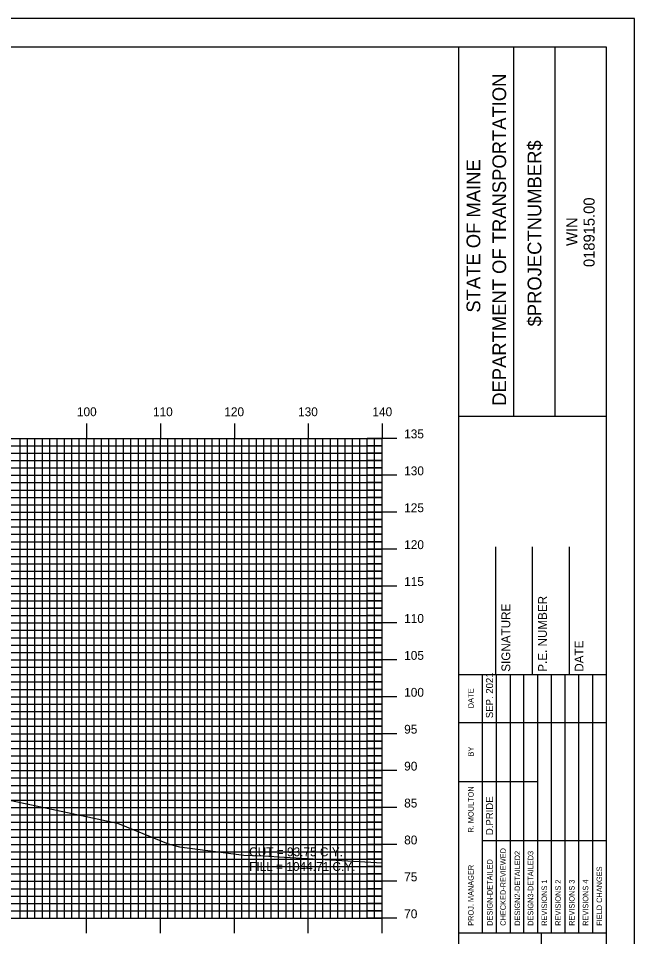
# Model space of a CAD drawing. Extents: x 858684 to 859027, y 364765 to 364985.
# Drawn here: x 858940.6 to 859024.1, y 364860.8 to 364985.2 of the extents above; entities that cross this region are included whole.
import ezdxf

# ---------------------------------------------------------------- set-up
doc = ezdxf.new("R2010")
doc.units = 0
for name, color, linetype in [('BORDER', 7, 'Continuous'), ('D_Text_Standard', 7, 'Continuous'), ('H_V ANNOTATION', 7, 'Continuous'), ('MAJOR', 7, 'Continuous'), ('MINOR', 7, 'Continuous'), ('PLOT BOUNDARY', 7, 'Continuous'), ('S_Roadway_Centerline', 7, 'Continuous')]:
    doc.layers.add(name, color=color, linetype=linetype)

msp = doc.modelspace()

# ---------------------------------------------------------------- linework, layer by layer
at = {"layer": 'BORDER'}
for p, q in [((859000.25, 364771.3), (859000.25, 364981.3)), ((859007.7, 364931.3), (859007.7, 364981.3)), ((859013.29, 364931.3), (859013.29, 364981.3)), ((859000.25, 364931.29), (859020.25, 364931.29)), ((859005.25, 364896.31), (859005.25, 364913.6)), ((859010.25, 364896.31), (859010.25, 364913.6)), ((859015.25, 364896.31), (859015.25, 364913.6)), ((859000.25, 364896.31), (859020.25, 364896.31)), ((859000.25, 364861.31), (859020.25, 364861.31)), ((859011.43, 364791.31), (859011.43, 364861.31))]:
    msp.add_line(p, q, dxfattribs=at)
msp.add_lwpolyline([(858700.25, 364771.3), (859020.25, 364771.3), (859020.25, 364981.3), (858700.25, 364981.3)], close=True, dxfattribs=at)
for points in [[(859003.48, 364889.81), (859003.48, 364896.31)], [(859005.34, 364861.31), (859005.34, 364896.31)], [(859007.21, 364896.31), (859007.21, 364861.31)], [(859009.07, 364861.31), (859009.07, 364896.31)], [(859010.93, 364861.31), (859010.93, 364896.31)], [(859012.8, 364861.31), (859012.8, 364896.31)], [(859014.66, 364861.31), (859014.66, 364896.31)], [(859016.52, 364861.31), (859016.52, 364896.31)], [(859018.39, 364861.31), (859018.39, 364896.31)], [(859003.48, 364861.31), (859003.48, 364894.9)], [(859000.25, 364889.81), (859020.25, 364889.81)], [(859000.25, 364881.81), (859003.48, 364881.81)], [(859003.48, 364881.81), (859010.93, 364881.81)], [(859003.48, 364873.81), (859020.25, 364873.81)]]:
    msp.add_lwpolyline(points, dxfattribs=at)
at = {"layer": 'MAJOR'}
for p, q in [((858949.85, 364930.31), (858949.85, 364928.3)), ((858959.85, 364930.31), (858959.85, 364928.3)), ((858969.85, 364930.31), (858969.85, 364928.3)), ((858979.85, 364930.31), (858979.85, 364928.3)), ((858989.85, 364930.31), (858989.85, 364928.3)), ((858709.85, 364928.3), (858989.85, 364928.3)), ((858709.85, 364928.3), (858989.85, 364928.3)), ((858949.85, 364863.3), (858949.85, 364928.3)), ((858959.85, 364863.3), (858959.85, 364928.3)), ((858969.85, 364863.3), (858969.85, 364928.3)), ((858979.85, 364863.3), (858979.85, 364928.3)), ((858991.85, 364928.3), (858987.84, 364928.3)), ((858989.85, 364863.3), (858989.85, 364928.3)), ((858989.85, 364863.3), (858989.85, 364928.3)), ((858709.85, 364923.3), (858989.85, 364923.3)), ((858991.85, 364923.3), (858987.84, 364923.3)), ((858709.85, 364918.3), (858989.85, 364918.3)), ((858991.85, 364918.3), (858987.84, 364918.3)), ((858709.85, 364913.3), (858989.85, 364913.3)), ((858991.85, 364913.3), (858987.84, 364913.3)), ((858709.85, 364908.3), (858989.85, 364908.3)), ((858991.85, 364908.3), (858987.84, 364908.3)), ((858709.85, 364903.3), (858989.85, 364903.3)), ((858991.85, 364903.3), (858987.84, 364903.3)), ((858709.85, 364898.3), (858989.85, 364898.3)), ((858991.85, 364898.3), (858987.84, 364898.3)), ((858709.85, 364893.3), (858989.85, 364893.3)), ((858991.85, 364893.3), (858987.84, 364893.3)), ((858709.85, 364888.3), (858989.85, 364888.3)), ((858991.85, 364888.3), (858987.84, 364888.3)), ((858709.85, 364883.3), (858989.85, 364883.3)), ((858991.85, 364883.3), (858987.84, 364883.3)), ((858709.85, 364878.3), (858989.85, 364878.3)), ((858991.85, 364878.3), (858987.84, 364878.3)), ((858709.85, 364873.3), (858989.85, 364873.3)), ((858991.85, 364873.3), (858987.84, 364873.3)), ((858709.85, 364868.3), (858989.85, 364868.3)), ((858991.85, 364868.3), (858987.84, 364868.3)), ((858709.85, 364863.3), (858989.85, 364863.3)), ((858709.85, 364863.3), (858989.85, 364863.3)), ((858949.85, 364861.3), (858949.85, 364863.3)), ((858959.85, 364861.3), (858959.85, 364863.3)), ((858969.85, 364861.3), (858969.85, 364863.3)), ((858979.85, 364861.3), (858979.85, 364863.3)), ((858991.85, 364863.3), (858987.84, 364863.3)), ((858989.85, 364861.3), (858989.85, 364863.3))]:
    msp.add_line(p, q, dxfattribs=at)
at = {"layer": 'MINOR'}
for p, q in [((858940.85, 364863.3), (858940.85, 364928.3)), ((858941.85, 364863.3), (858941.85, 364928.3)), ((858942.85, 364863.3), (858942.85, 364928.3)), ((858943.85, 364863.3), (858943.85, 364928.3)), ((858944.85, 364863.3), (858944.85, 364928.3)), ((858945.85, 364863.3), (858945.85, 364928.3)), ((858946.85, 364863.3), (858946.85, 364928.3)), ((858947.85, 364863.3), (858947.85, 364928.3)), ((858948.85, 364863.3), (858948.85, 364928.3)), ((858950.85, 364863.3), (858950.85, 364928.3)), ((858951.85, 364863.3), (858951.85, 364928.3)), ((858952.85, 364863.3), (858952.85, 364928.3)), ((858953.85, 364863.3), (858953.85, 364928.3)), ((858954.85, 364863.3), (858954.85, 364928.3)), ((858955.85, 364863.3), (858955.85, 364928.3)), ((858956.85, 364863.3), (858956.85, 364928.3)), ((858957.85, 364863.3), (858957.85, 364928.3)), ((858958.85, 364863.3), (858958.85, 364928.3)), ((858960.85, 364863.3), (858960.85, 364928.3)), ((858961.85, 364863.3), (858961.85, 364928.3)), ((858962.85, 364863.3), (858962.85, 364928.3)), ((858963.85, 364863.3), (858963.85, 364928.3)), ((858964.85, 364863.3), (858964.85, 364928.3)), ((858965.85, 364863.3), (858965.85, 364928.3)), ((858966.85, 364863.3), (858966.85, 364928.3)), ((858967.85, 364863.3), (858967.85, 364928.3)), ((858968.85, 364863.3), (858968.85, 364928.3)), ((858970.85, 364863.3), (858970.85, 364928.3)), ((858971.85, 364863.3), (858971.85, 364928.3)), ((858972.85, 364863.3), (858972.85, 364928.3)), ((858973.85, 364863.3), (858973.85, 364928.3)), ((858974.85, 364863.3), (858974.85, 364928.3)), ((858975.85, 364863.3), (858975.85, 364928.3)), ((858976.85, 364863.3), (858976.85, 364928.3)), ((858977.85, 364863.3), (858977.85, 364928.3)), ((858978.85, 364863.3), (858978.85, 364928.3)), ((858980.85, 364863.3), (858980.85, 364928.3)), ((858981.85, 364863.3), (858981.85, 364928.3)), ((858982.85, 364863.3), (858982.85, 364928.3)), ((858983.85, 364863.3), (858983.85, 364928.3)), ((858984.85, 364863.3), (858984.85, 364928.3)), ((858985.85, 364863.3), (858985.85, 364928.3)), ((858986.85, 364863.3), (858986.85, 364928.3)), ((858987.85, 364863.3), (858987.85, 364928.3)), ((858988.85, 364863.3), (858988.85, 364928.3)), ((858709.85, 364927.3), (858989.85, 364927.3)), ((858989.85, 364927.3), (858987.84, 364927.3)), ((858709.85, 364926.3), (858989.85, 364926.3)), ((858989.85, 364926.3), (858987.84, 364926.3)), ((858709.85, 364925.3), (858989.85, 364925.3)), ((858709.85, 364924.3), (858989.85, 364924.3)), ((858989.85, 364925.3), (858987.84, 364925.3)), ((858989.85, 364924.3), (858987.84, 364924.3)), ((858709.85, 364922.3), (858989.85, 364922.3)), ((858989.85, 364922.3), (858987.84, 364922.3)), ((858709.85, 364921.3), (858989.85, 364921.3)), ((858989.85, 364921.3), (858987.84, 364921.3)), ((858709.85, 364920.3), (858989.85, 364920.3)), ((858989.85, 364920.3), (858987.84, 364920.3)), ((858709.85, 364919.3), (858989.85, 364919.3)), ((858989.85, 364919.3), (858987.84, 364919.3)), ((858709.85, 364917.3), (858989.85, 364917.3)), ((858989.85, 364917.3), (858987.84, 364917.3)), ((858709.85, 364916.3), (858989.85, 364916.3)), ((858989.85, 364916.3), (858987.84, 364916.3)), ((858709.85, 364915.3), (858989.85, 364915.3)), ((858989.85, 364915.3), (858987.84, 364915.3)), ((858709.85, 364914.3), (858989.85, 364914.3)), ((858989.85, 364914.3), (858987.84, 364914.3)), ((858709.85, 364912.3), (858989.85, 364912.3)), ((858989.85, 364912.3), (858987.84, 364912.3)), ((858709.85, 364911.3), (858989.85, 364911.3)), ((858989.85, 364911.3), (858987.84, 364911.3)), ((858709.85, 364910.3), (858989.85, 364910.3)), ((858989.85, 364910.3), (858987.84, 364910.3)), ((858709.85, 364909.3), (858989.85, 364909.3)), ((858989.85, 364909.3), (858987.84, 364909.3)), ((858709.85, 364907.3), (858989.85, 364907.3)), ((858989.85, 364907.3), (858987.84, 364907.3)), ((858709.85, 364906.3), (858989.85, 364906.3)), ((858989.85, 364906.3), (858987.84, 364906.3)), ((858709.85, 364905.3), (858989.85, 364905.3)), ((858989.85, 364905.3), (858987.84, 364905.3)), ((858709.85, 364904.3), (858989.85, 364904.3)), ((858989.85, 364904.3), (858987.84, 364904.3)), ((858709.85, 364902.3), (858989.85, 364902.3)), ((858989.85, 364902.3), (858987.84, 364902.3)), ((858709.85, 364901.3), (858989.85, 364901.3)), ((858989.85, 364901.3), (858987.84, 364901.3)), ((858709.85, 364900.3), (858989.85, 364900.3)), ((858989.85, 364900.3), (858987.84, 364900.3)), ((858709.85, 364899.3), (858989.85, 364899.3)), ((858989.85, 364899.3), (858987.84, 364899.3)), ((858709.85, 364897.3), (858989.85, 364897.3)), ((858989.85, 364897.3), (858987.84, 364897.3)), ((858709.85, 364896.3), (858989.85, 364896.3)), ((858989.85, 364896.3), (858987.84, 364896.3)), ((858709.85, 364895.3), (858989.85, 364895.3)), ((858989.85, 364895.3), (858987.84, 364895.3)), ((858709.85, 364894.3), (858989.85, 364894.3)), ((858989.85, 364894.3), (858987.84, 364894.3)), ((858709.85, 364892.3), (858989.85, 364892.3)), ((858989.85, 364892.3), (858987.84, 364892.3)), ((858709.85, 364891.3), (858989.85, 364891.3)), ((858989.85, 364891.3), (858987.84, 364891.3)), ((858709.85, 364890.3), (858989.85, 364890.3)), ((858989.85, 364890.3), (858987.84, 364890.3)), ((858709.85, 364889.3), (858989.85, 364889.3)), ((858989.85, 364889.3), (858987.84, 364889.3)), ((858709.85, 364887.3), (858989.85, 364887.3)), ((858989.85, 364887.3), (858987.84, 364887.3)), ((858709.85, 364886.3), (858989.85, 364886.3)), ((858989.85, 364886.3), (858987.84, 364886.3)), ((858709.85, 364885.3), (858989.85, 364885.3)), ((858989.85, 364885.3), (858987.84, 364885.3)), ((858709.85, 364884.3), (858989.85, 364884.3)), ((858989.85, 364884.3), (858987.84, 364884.3)), ((858709.85, 364882.3), (858989.85, 364882.3)), ((858989.85, 364882.3), (858987.84, 364882.3)), ((858709.85, 364881.3), (858989.85, 364881.3)), ((858989.85, 364881.3), (858987.84, 364881.3)), ((858709.85, 364880.3), (858989.85, 364880.3)), ((858989.85, 364880.3), (858987.84, 364880.3)), ((858709.85, 364879.3), (858989.85, 364879.3)), ((858989.85, 364879.3), (858987.84, 364879.3)), ((858709.85, 364877.3), (858989.85, 364877.3)), ((858989.85, 364877.3), (858987.84, 364877.3)), ((858709.85, 364876.3), (858989.85, 364876.3)), ((858989.85, 364876.3), (858987.84, 364876.3)), ((858709.85, 364875.3), (858989.85, 364875.3)), ((858989.85, 364875.3), (858987.84, 364875.3)), ((858709.85, 364874.3), (858989.85, 364874.3)), ((858989.85, 364874.3), (858987.84, 364874.3)), ((858709.85, 364872.3), (858989.85, 364872.3)), ((858989.85, 364872.3), (858987.84, 364872.3)), ((858709.85, 364871.3), (858989.85, 364871.3)), ((858989.85, 364871.3), (858987.84, 364871.3)), ((858709.85, 364870.3), (858989.85, 364870.3)), ((858989.85, 364870.3), (858987.84, 364870.3)), ((858709.85, 364869.3), (858989.85, 364869.3)), ((858989.85, 364869.3), (858987.84, 364869.3)), ((858709.85, 364867.3), (858989.85, 364867.3)), ((858989.85, 364867.3), (858987.84, 364867.3)), ((858709.85, 364866.3), (858989.85, 364866.3)), ((858989.85, 364866.3), (858987.84, 364866.3)), ((858709.85, 364865.3), (858989.85, 364865.3)), ((858989.85, 364865.3), (858987.84, 364865.3)), ((858709.85, 364864.3), (858989.85, 364864.3)), ((858989.85, 364864.3), (858987.84, 364864.3))]:
    msp.add_line(p, q, dxfattribs=at)
at = {"layer": 'PLOT BOUNDARY'}
msp.add_lwpolyline([(858684.06, 364765.18), (859024.06, 364765.18), (859024.06, 364985.18), (858684.06, 364985.18)], close=True, dxfattribs=at)
at = {"layer": 'S_Roadway_Centerline'}
msp.add_lwpolyline([(858791.46, 364917.22), (858801.59, 364917.48), (858818, 364918.14), (858824.58, 364918.58), (858838.64, 364918.92), (858844.05, 364919.02), (858850.88, 364916.87), (858859.4, 364913.15), (858875.43, 364904.86), (858879.29, 364902.99), (858899.1, 364893.63), (858900.38, 364893.08), (858910.71, 364888.45), (858915.53, 364886.48), (858923.68, 364882.65), (858954.04, 364876.19), (858960.9, 364873.39), (858962.43, 364872.98), (858971.15, 364871.85), (858973.79, 364871.77), (858976.66, 364871.57), (858989.85, 364870.79)], dxfattribs=at)

# ---------------------------------------------------------------- texts
at = {"layer": 'BORDER'}
for s, height, p in [('DEPARTMENT OF TRANSPORTATION', 1.8635, (859006.66, 364932.71)), ('$PROJECTNUMBER$', 1.8635, (859011.43, 364943.46)), ('STATE OF MAINE', 1.8635, (859003.16, 364945.33)), ('018915.00', 1.491, (859018.64, 364951.5)), ('WIN', 1.491, (859016.32, 364954.36)), ('P.E. NUMBER', 1.1811, (859012.17, 364896.69)), ('SIGNATURE', 1.181, (859007.21, 364896.69)), ('DATE', 1.181, (859017.13, 364896.69)), ('SEP. 2021', 0.969, (859004.89, 364890.4)), ('DATE', 0.743, (859002.26, 364891.72)), ('BY', 0.743, (859002.26, 364885.18)), ('R. MOULTON', 0.745, (859002.26, 364874.91)), ('D.PRIDE', 0.969, (859004.89, 364874.55)), ('CHECKED-REVIEWED', 0.7455, (859006.61, 364862.28)), ('DESIGN2-DETAILED2', 0.7455, (859008.55, 364862.28)), ('DESIGN3-DETAILED3', 0.7455, (859010.34, 364862.28)), ('DESIGN-DETAILED', 0.7455, (859004.82, 364862.28)), ('PROJ. MANAGER', 0.7455, (859002.26, 364862.28)), ('FIELD CHANGES', 0.7455, (859019.65, 364862.28)), ('REVISIONS 1', 0.7455, (859012.2, 364862.28)), ('REVISIONS 2', 0.7455, (859014.06, 364862.28)), ('REVISIONS 3', 0.7455, (859015.93, 364862.28)), ('REVISIONS 4', 0.7455, (859017.79, 364862.28))]:
    msp.add_text(s, height=height, rotation=90, dxfattribs=at).set_placement(p)
at = {"layer": 'D_Text_Standard'}
for s, p in [('CUT = 93.75 C.Y.', (858971.85, 364871.7)), ('FILL = 1044.71 C.Y.', (858971.85, 364869.71))]:
    msp.add_text(s, height=1.2, dxfattribs=at).set_placement(p)
at = {"layer": 'H_V ANNOTATION'}
for s, p in [('100', (858948.53, 364931.3)), ('110', (858958.83, 364931.3)), ('120', (858968.49, 364931.3)), ('130', (858978.48, 364931.3)), ('140', (858988.55, 364931.3)), ('135', (858992.85, 364928.3)), ('130', (858992.85, 364923.3)), ('125', (858992.85, 364918.3)), ('120', (858992.85, 364913.3)), ('115', (858992.85, 364908.3)), ('110', (858992.85, 364903.3)), ('105', (858992.85, 364898.3)), ('100', (858992.85, 364893.3)), ('95', (858992.85, 364888.3)), ('90', (858992.85, 364883.3)), ('85', (858992.85, 364878.3)), ('80', (858992.85, 364873.3)), ('75', (858992.85, 364868.3)), ('70', (858992.85, 364863.3))]:
    msp.add_text(s, height=1.2, dxfattribs=at).set_placement(p)

doc.saveas('drawing.dxf')
